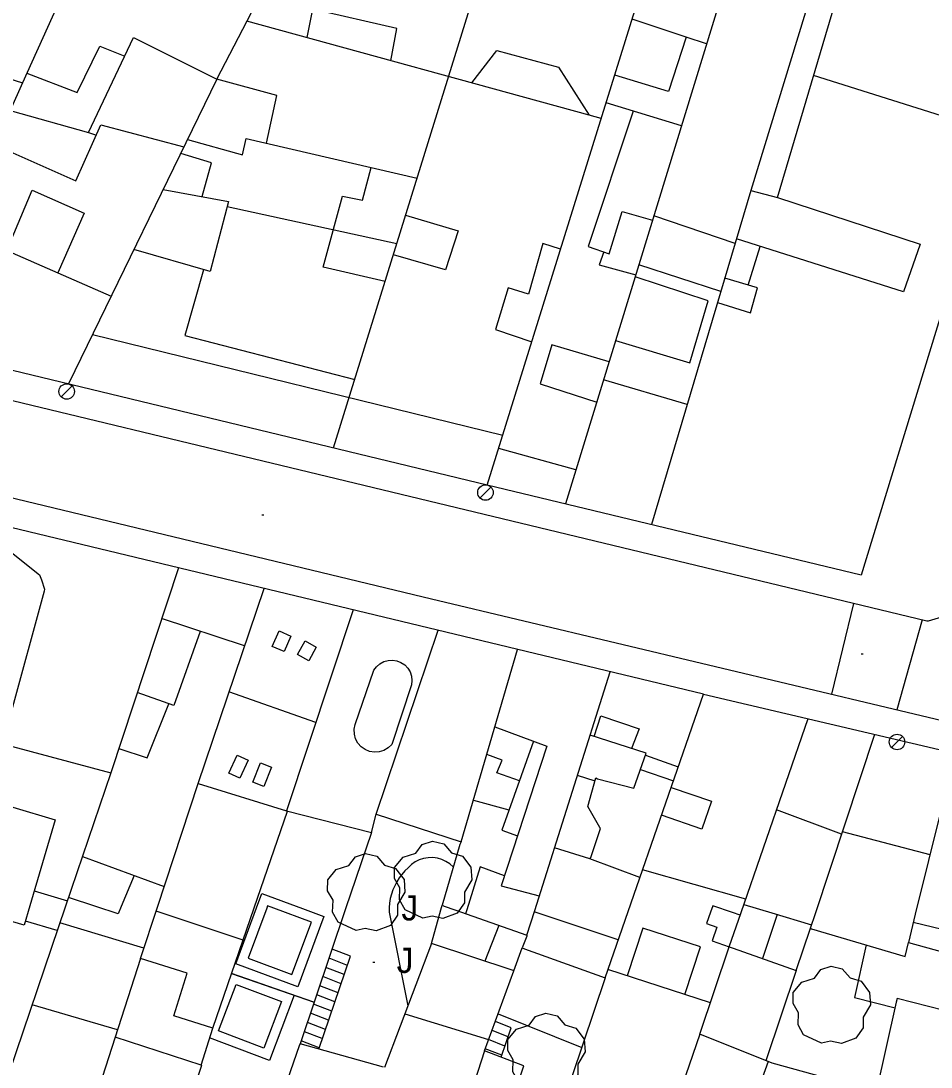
# Model space of a CAD drawing. Extents: x 431390 to 432653, y 4586754 to 4589600.
# Drawn here: x 432045.3 to 432092.3, y 4587636.5 to 4587690.5 of the extents above; entities that cross this region are included whole.
import ezdxf

# ---------------------------------------------------------------- set-up
doc = ezdxf.new("R2010")
doc.units = 0
for name, color, linetype in [('COM_17LS_LN', 7, 'Continuous'), ('COM_51_LN', 7, 'Continuous'), ('CON_01_LN', 7, 'Continuous'), ('CON_01FI_LN', 7, 'Continuous'), ('CON_03_LN', 7, 'Continuous'), ('CON_04_LN', 7, 'Continuous'), ('CON_07_LN', 7, 'Continuous'), ('CON_14LS_LN', 7, 'Continuous'), ('CON_15_LN', 7, 'Continuous'), ('CON_16_LN', 7, 'Continuous'), ('CON_23_LN', 7, 'Continuous'), ('CON_29_LN', 7, 'Continuous'), ('ENE_06_PT', 7, 'Continuous'), ('HID_11EX_LN', 7, 'Continuous'), ('HID_11IN_LN', 7, 'Continuous'), ('ORO_03_PT', 7, 'Continuous'), ('TOP_15JA_TX', 7, 'Continuous'), ('VEG_03_PT', 7, 'Continuous'), ('VEG_04_LN', 7, 'Continuous'), ('VEG_06_LN', 7, 'Continuous')]:
    doc.layers.add(name, color=color, linetype=linetype)

msp = doc.modelspace()

# ---------------------------------------------------------------- linework, layer by layer
at = {"layer": 'COM_17LS_LN'}
for points in [[(432006.024, 4587680.292), (432041.411, 4587756.509), (432044.673, 4587755.098), (432041.441, 4587748.129), (432031.405, 4587726.494), (432019.334, 4587700.469), (432009.569, 4587679.418), (432092.063, 4587659.53)], [(432092.063, 4587659.53), (432092.146, 4587659.541), (432092.826, 4587659.752), (432093.143, 4587659.912), (432093.715, 4587660.335), (432094.179, 4587660.874), (432094.362, 4587661.179), (432100.29, 4587680.016), (432111, 4587714.962), (432115.403, 4587729.599), (432115.334, 4587730.858), (432115.129, 4587731.674), (432114.803, 4587732.45), (432114.363, 4587733.167), (432113.819, 4587733.81), (432098.948, 4587740.984), (432087.838, 4587745.869), (432079.478, 4587749.815), (432077.122, 4587750.796)], [(431996.705, 4587653.49), (432007.414, 4587674.901), (432066.476, 4587660.674)], [(432066.476, 4587660.674), (432114.167, 4587649.302), (432121.083, 4587647.603), (432135.943, 4587643.954), (432158.866, 4587638.419)]]:
    msp.add_lwpolyline(points, dxfattribs=at)
at = {"layer": 'COM_51_LN'}
for points in [[(432087.153, 4587655.744), (432088.291, 4587660.441)], [(432091.821, 4587659.588), (432090.513, 4587654.942)]]:
    msp.add_lwpolyline(points, dxfattribs=at)
at = {"layer": 'CON_01_LN'}
for points in [[(432021.338, 4587700.513), (432047.183, 4587756.23), (432074.462, 4587750.012), (432092.863, 4587741.826), (432089.971, 4587731.966), (432092.685, 4587729.526), (432096.818, 4587726.785), (432106.854, 4587721.265), (432088.661, 4587661.894), (432069.351, 4587666.555)], [(432069.351, 4587666.555), (432012.008, 4587680.398), (432019.086, 4587695.657)], [(432080.515, 4587655.754), (432008.507, 4587673.078)], [(432080.515, 4587655.754), (432121.07, 4587646.224)]]:
    msp.add_lwpolyline(points, dxfattribs=at)
at = {"layer": 'CON_01FI_LN'}
for points in [[(432037.686, 4587692.072), (432036.767, 4587689.999), (432039.8, 4587688.515), (432040.023, 4587689.014), (432045.332, 4587687.328), (432044.693, 4587685.898), (432048.742, 4587684.772), (432051.08, 4587689.672), (432055.373, 4587687.519), (432063.231, 4587702.643)], [(432086.763, 4587694.198), (432082.971, 4587681.767), (432084.341, 4587681.402), (432088.05, 4587693.921), (432086.763, 4587694.198)], [(432047.563, 4587644.797), (432044.268, 4587635.081), (432006.82, 4587644.663), (432007.084, 4587645.187), (432015.694, 4587662.285), (432015.737, 4587662.272), (432034.19, 4587657.797), (432034.86, 4587660.208), (432035.137, 4587660.172), (432037.16, 4587659.697), (432037.143, 4587659.656), (432036.593, 4587657.168), (432036.755, 4587657.127), (432038.472, 4587656.7), (432038.755, 4587657.502), (432038.809, 4587657.469), (432040.297, 4587657.161), (432039.882, 4587656.377), (432039.414, 4587654.497), (432039.468, 4587654.474), (432049.901, 4587651.69), (432047.563, 4587644.797)], [(432053.422, 4587633.03), (432054.602, 4587636.574), (432054.567, 4587636.585), (432055.166, 4587638.492), (432053.15, 4587639.125), (432053.842, 4587641.329), (432051.434, 4587642.085), (432052.31, 4587644.752), (432054.407, 4587651.139)], [(432054.407, 4587651.139), (432058.983, 4587649.713), (432063.36, 4587648.605), (432063.605, 4587649.557), (432067.998, 4587648.114), (432067.93, 4587647.98), (432067.017, 4587644.843), (432067.116, 4587644.798), (432067.67, 4587644.604), (432071.398, 4587643.296), (432071.385, 4587643.243), (432071.151, 4587642.636), (432071.275, 4587642.597), (432075.437, 4587641.097), (432073.721, 4587635.974)], [(432080.339, 4587638.19), (432081.853, 4587642.698), (432082.054, 4587642.622), (432085.313, 4587641.466), (432086.042, 4587643.651), (432086.104, 4587643.625), (432090.935, 4587642.193), (432091.104, 4587642.919), (432096.913, 4587641.324), (432096.863, 4587641.194), (432096.183, 4587638.584), (432090.527, 4587640.017), (432090.482, 4587639.827), (432089.44, 4587635.201), (432084.065, 4587636.68), (432080.339, 4587638.19)], [(432070.208, 4587633.421), (432071.231, 4587636.549), (432071.178, 4587636.563), (432069.208, 4587637.32), (432070.728, 4587641.451), (432070.695, 4587641.471), (432066.472, 4587642.862), (432064.04, 4587636.456)], [(432063.986, 4587636.472), (432059.689, 4587637.682), (432059.654, 4587637.628), (432057.715, 4587632.046)]]:
    msp.add_lwpolyline(points, dxfattribs=at)
at = {"layer": 'CON_03_LN'}
for points in [[(432069.351, 4587666.555), (432083.88, 4587713.291)], [(432061.406, 4587668.473), (432075.16, 4587712.871)], [(432083.367, 4587698.099), (432073.392, 4587665.58)], [(432055.373, 4587687.519), (432047.718, 4587671.777)], [(432095.662, 4587684.74), (432086.209, 4587687.707)], [(432082.971, 4587681.767), (432077.833, 4587664.508)], [(432053.389, 4587662.28), (432049.901, 4587651.69)], [(432054.407, 4587651.139), (432057.817, 4587661.215)], [(432062.414, 4587660.109), (432058.983, 4587649.713)], [(432063.605, 4587649.557), (432066.808, 4587659.052)], [(432067.998, 4587648.114), (432070.907, 4587658.065)], [(432071.398, 4587643.296), (432071.799, 4587644.564), (432075.704, 4587656.911)], [(432075.437, 4587641.097), (432076.622, 4587644.518), (432080.515, 4587655.754)], [(432081.853, 4587642.698), (432082.461, 4587644.461), (432085.919, 4587654.484)], [(432086.042, 4587643.651), (432086.298, 4587644.424), (432089.365, 4587653.674)], [(432093.517, 4587652.699), (432091.463, 4587644.375), (432091.104, 4587642.919)], [(432051.613, 4587642.629), (432047.273, 4587643.942)], [(432051.434, 4587642.085), (432045.508, 4587623.69)], [(432080.878, 4587639.796), (432075.586, 4587641.528)], [(432080.339, 4587638.19), (432073.015, 4587616.91)], [(432069.208, 4587637.32), (432068.171, 4587634.125)], [(432083.856, 4587636.765), (432082.494, 4587632.997)]]:
    msp.add_lwpolyline(points, dxfattribs=at)
at = {"layer": 'CON_04_LN'}
for points in [[(432064.373, 4587688.477), (432064.669, 4587690.14), (432060.314, 4587691.142), (432060.028, 4587689.67)], [(432074.611, 4587685.667), (432056.932, 4587690.52)], [(432079.625, 4587689.692), (432076.832, 4587690.618)], [(432079.625, 4587689.692), (432078.71, 4587686.886), (432075.933, 4587687.727)], [(432080.681, 4587689.342), (432079.625, 4587689.692)], [(432068.559, 4587687.328), (432069.839, 4587689), (432073.026, 4587688.139), (432074.611, 4587685.667)], [(432057.947, 4587684.215), (432058.484, 4587686.685), (432055.373, 4587687.519)], [(432076.892, 4587685.877), (432074.57, 4587678.877), (432075.655, 4587678.492), (432076.321, 4587680.686), (432077.889, 4587680.239)], [(432079.386, 4587685.12), (432075.49, 4587686.302)], [(432075.239, 4587685.495), (432074.611, 4587685.667)], [(432043.898, 4587684.124), (432048.088, 4587682.264), (432049.392, 4587685.166), (432053.673, 4587684.023)], [(432048.742, 4587684.772), (432049.153, 4587684.635)], [(432053.857, 4587684.402), (432056.706, 4587683.611), (432056.895, 4587684.46), (432065.722, 4587682.406)], [(432054.623, 4587681.454), (432055.098, 4587683.197), (432053.51, 4587683.689)], [(432064.072, 4587677.078), (432060.878, 4587677.817), (432061.866, 4587681.479), (432062.901, 4587681.277), (432063.354, 4587682.957)], [(432044.533, 4587678.666), (432045.829, 4587681.781), (432048.52, 4587680.597), (432047.155, 4587677.517)], [(432052.6, 4587681.817), (432055.987, 4587681.21), (432055.036, 4587677.579), (432051.096, 4587678.724)], [(432084.341, 4587681.402), (432091.72, 4587678.994), (432090.858, 4587676.542), (432082.227, 4587679.269)], [(432065.128, 4587680.489), (432067.853, 4587679.688), (432067.188, 4587677.676), (432064.497, 4587678.452)], [(432082.155, 4587679.027), (432077.959, 4587680.467)], [(432073.14, 4587678.744), (432072.219, 4587679.033), (432071.478, 4587676.412), (432070.421, 4587676.739), (432069.772, 4587674.584), (432071.649, 4587673.948)], [(432082.822, 4587676.882), (432083.446, 4587678.884)], [(432044.533, 4587678.666), (432047.155, 4587677.517)], [(432075.364, 4587678.595), (432075.125, 4587677.934), (432077.021, 4587677.41)], [(432081.417, 4587676.547), (432077.18, 4587677.929)], [(432054.697, 4587677.677), (432053.729, 4587674.274), (432062.502, 4587672.011)], [(432075.981, 4587674.019), (432079.809, 4587672.864), (432080.757, 4587676.068), (432076.992, 4587677.317)], [(432081.25, 4587675.985), (432082.941, 4587675.454), (432083.312, 4587676.738), (432081.622, 4587677.236)], [(432048.959, 4587674.329), (432070.152, 4587669.131)], [(432075.641, 4587672.912), (432072.689, 4587673.798), (432072.076, 4587671.786), (432075.003, 4587670.831)], [(432073.929, 4587667.332), (432069.939, 4587668.447)], [(432044.454, 4587663.281), (432044.858, 4587662.991), (432046.225, 4587661.91), (432046.324, 4587661.657), (432046.467, 4587661.177), (432046.463, 4587661.068), (432044.713, 4587654.69), (432044.513, 4587654.761), (432041.515, 4587655.419), (432039.882, 4587656.377)], [(432056.81, 4587658.24), (432052.523, 4587659.651)], [(432054.523, 4587658.993), (432053.158, 4587655.159), (432051.264, 4587655.829)], [(432058.85, 4587657.945), (432058.238, 4587658.216), (432058.591, 4587659.015), (432059.203, 4587658.743), (432058.85, 4587657.945)], [(432060.123, 4587657.472), (432059.542, 4587657.793), (432059.936, 4587658.506), (432060.516, 4587658.185), (432060.123, 4587657.472)], [(432063.49, 4587656.984), (432063.626, 4587657.169), (432063.798, 4587657.32), (432064, 4587657.43), (432064.221, 4587657.494), (432064.45, 4587657.509), (432064.677, 4587657.473), (432064.891, 4587657.39), (432065.082, 4587657.262), (432065.24, 4587657.096), (432065.359, 4587656.899), (432065.432, 4587656.681), (432065.457, 4587656.453), (432065.432, 4587656.225), (432064.411, 4587653.144), (432064.228, 4587652.972), (432064.011, 4587652.846), (432063.771, 4587652.772), (432063.52, 4587652.755), (432063.272, 4587652.795), (432063.04, 4587652.89), (432062.836, 4587653.035), (432062.669, 4587653.223), (432062.55, 4587653.444), (432062.484, 4587653.686), (432062.474, 4587653.937), (432062.522, 4587654.184), (432063.49, 4587656.984)], [(432050.315, 4587652.947), (432051.775, 4587652.467), (432052.9, 4587655.25)], [(432074.878, 4587653.557), (432075.217, 4587654.632), (432077.204, 4587653.963), (432076.796, 4587652.944)], [(432069.735, 4587654.055), (432072.427, 4587653.062), (432070.067, 4587645.85), (432072.038, 4587645.321)], [(432077.233, 4587646.282), (432074.654, 4587647.238), (432074.707, 4587647.306), (432075.194, 4587648.814), (432075.168, 4587648.859), (432074.538, 4587649.937), (432074.966, 4587651.427), (432075.051, 4587651.37), (432076.929, 4587650.899), (432077.563, 4587652.699), (432074.665, 4587653.625)], [(432071.741, 4587653.315), (432070.096, 4587648.73), (432070.911, 4587648.43)], [(432056.423, 4587652.601), (432056.99, 4587652.346), (432056.567, 4587651.406), (432056, 4587651.66), (432056.423, 4587652.601)], [(432071.007, 4587651.27), (432069.85, 4587651.687), (432070.113, 4587652.338), (432069.319, 4587652.632)], [(432077.525, 4587652.59), (432079.215, 4587652.003)], [(432057.64, 4587652.205), (432058.208, 4587651.983), (432057.813, 4587650.974), (432057.245, 4587651.195), (432057.64, 4587652.205)], [(432077.267, 4587651.859), (432078.962, 4587651.271)], [(432074.916, 4587651.254), (432074.006, 4587651.541)], [(432078.845, 4587650.934), (432080.926, 4587650.214), (432080.43, 4587648.782), (432078.349, 4587649.502)], [(432068.631, 4587650.279), (432070.47, 4587649.772)], [(432074.654, 4587647.238), (432072.827, 4587647.815)], [(432048.432, 4587647.359), (432052.656, 4587645.805)], [(432070.232, 4587646.355), (432068.988, 4587646.823), (432068.289, 4587644.598), (432068.229, 4587644.408)], [(432082.703, 4587645.163), (432077.371, 4587646.681)], [(432051.104, 4587646.376), (432050.435, 4587644.77), (432050.283, 4587644.404), (432049.134, 4587644.782), (432047.716, 4587645.249)], [(432082.415, 4587644.327), (432082.014, 4587644.466), (432081, 4587644.816), (432080.883, 4587644.477), (432080.681, 4587643.893), (432081.213, 4587643.708), (432080.968, 4587643.005), (432081.853, 4587642.698)], [(432082.606, 4587644.88), (432084.058, 4587644.446), (432086.103, 4587643.835)], [(432076.114, 4587643.051), (432071.777, 4587644.495)], [(432084.321, 4587644.367), (432083.57, 4587642.084)], [(432105.114, 4587640.636), (432091.36, 4587643.957)], [(432079.563, 4587640.226), (432080.369, 4587642.687), (432077.388, 4587643.663), (432076.582, 4587641.202)], [(432050.251, 4587638.414), (432045.835, 4587639.701)], [(432054.567, 4587636.585), (432050.128, 4587638.031)]]:
    msp.add_lwpolyline(points, dxfattribs=at)
at = {"layer": 'CON_07_LN'}
for points in [[(432045.563, 4587687.839), (432048.165, 4587686.835), (432049.328, 4587689.234), (432050.622, 4587688.712)], [(432043.239, 4587644.448), (432043.353, 4587644.838), (432044.833, 4587649.904), (432047.021, 4587649.264), (432045.721, 4587644.815), (432045.427, 4587643.808), (432043.239, 4587644.448)], [(432045.947, 4587645.589), (432047.659, 4587645.079)], [(432047.135, 4587643.534), (432045.487, 4587644.015)], [(432069.947, 4587643.805), (432069.223, 4587641.956)], [(432070.728, 4587641.451), (432071.151, 4587642.636)], [(432088.917, 4587642.791), (432088.321, 4587640.076), (432090.418, 4587639.545)]]:
    msp.add_lwpolyline(points, dxfattribs=at)
at = {"layer": 'CON_14LS_LN'}
msp.add_lwpolyline([(432056.731, 4587643.041), (432052.238, 4587644.533)], dxfattribs=at)
at = {"layer": 'CON_15_LN'}
msp.add_lwpolyline([(432049.94, 4587697.527), (432045.332, 4587687.328)], dxfattribs=at)
at = {"layer": 'CON_16_LN'}
for points in [[(432055.166, 4587638.492), (432057.303, 4587644.703), (432059.023, 4587649.703)], [(432063.36, 4587648.605), (432062.033, 4587644.658), (432059.689, 4587637.682)], [(432066.472, 4587642.862), (432066.953, 4587644.611), (432067.017, 4587644.843)], [(432056.137, 4587641.314), (432060.41, 4587639.828)], [(432085.313, 4587641.466), (432083.745, 4587636.81)], [(432069.911, 4587639.232), (432074.228, 4587637.488)]]:
    msp.add_lwpolyline(points, dxfattribs=at)
at = {"layer": 'CON_23_LN'}
for points in [[(432060.64, 4587637.414), (432062.289, 4587642.211), (432061.335, 4587642.581)], [(432062.126, 4587641.737), (432061.175, 4587642.106)], [(432061.963, 4587641.264), (432061.016, 4587641.632)], [(432061.801, 4587640.791), (432060.857, 4587641.157)], [(432061.638, 4587640.318), (432060.697, 4587640.683)], [(432061.476, 4587639.845), (432060.538, 4587640.208)], [(432061.313, 4587639.372), (432060.378, 4587639.734)], [(432061.15, 4587638.899), (432060.219, 4587639.26)], [(432060.825, 4587637.952), (432059.9, 4587638.311)], [(432060.988, 4587638.426), (432060.06, 4587638.785)], [(432070.421, 4587638.039), (432069.594, 4587638.368)], [(432070.063, 4587636.991), (432070.583, 4587638.513), (432069.766, 4587638.838)], [(432060.662, 4587637.478), (432059.741, 4587637.836)], [(432070.259, 4587637.566), (432069.421, 4587637.899)], [(432070.097, 4587637.092), (432069.248, 4587637.43)]]:
    msp.add_lwpolyline(points, dxfattribs=at)
at = {"layer": 'CON_29_LN'}
for points in [[(432064.671, 4587679.012), (432055.914, 4587680.933)], [(432047.155, 4587677.517), (432049.92, 4587676.306)], [(432079.681, 4587670.716), (432075.356, 4587671.983)], [(432060.49, 4587654.278), (432056.006, 4587655.863)], [(432087.652, 4587648.507), (432084.293, 4587649.77)], [(432092.222, 4587647.452), (432087.696, 4587648.641)], [(432065.092, 4587639.227), (432069.421, 4587637.899)]]:
    msp.add_lwpolyline(points, dxfattribs=at)
at = {"layer": 'ENE_06_PT'}
for p, q in [((432047.906, 4587671.671), (432047.34, 4587671.105)), ((432069.539, 4587666.449), (432068.973, 4587665.883)), ((432090.801, 4587653.562), (432090.235, 4587652.996))]:
    msp.add_line(p, q, dxfattribs=at)
for centre in [(432047.623, 4587671.388), (432069.256, 4587666.166), (432090.518, 4587653.279)]:
    msp.add_circle(centre, 0.4, dxfattribs=at)
at = {"layer": 'HID_11EX_LN'}
for points in [[(432059.797, 4587644.679), (432060.903, 4587644.27), (432059.554, 4587640.629), (432056.353, 4587641.811), (432057.423, 4587644.702), (432057.702, 4587645.455), (432059.797, 4587644.679)], [(432059.37, 4587640.19), (432058.096, 4587636.819), (432055.007, 4587637.987)]]:
    msp.add_lwpolyline(points, dxfattribs=at)
at = {"layer": 'HID_11IN_LN'}
for points in [[(432058.322, 4587644.694), (432057.997, 4587644.814), (432057.954, 4587644.697), (432056.995, 4587642.107), (432059.26, 4587641.27), (432060.262, 4587643.976), (432058.322, 4587644.694)], [(432057.806, 4587637.463), (432055.464, 4587638.349), (432056.372, 4587640.751), (432058.714, 4587639.864), (432057.806, 4587637.463)]]:
    msp.add_lwpolyline(points, dxfattribs=at)
at = {"layer": 'ORO_03_PT'}
for p, q in [((432057.71, 4587665.019), (432057.81, 4587665.019)), ((432088.672, 4587657.83), (432088.772, 4587657.83)), ((432063.433, 4587641.896), (432063.533, 4587641.896))]:
    msp.add_line(p, q, dxfattribs=at)
at = {"layer": 'VEG_03_PT'}
for points in [[(432066.028, 4587644.169), (432065.101, 4587644.604), (432064.813, 4587645.125), (432064.836, 4587645.739), (432064.554, 4587646.231), (432064.562, 4587646.794), (432065.003, 4587647.329), (432065.656, 4587647.533), (432065.991, 4587647.984), (432066.517, 4587648.154), (432067.097, 4587648.021), (432067.497, 4587647.555), (432068.071, 4587647.385), (432068.505, 4587646.802), (432068.554, 4587646.16), (432068.171, 4587645.513), (432068.171, 4587644.963), (432067.799, 4587644.429), (432067.06, 4587644.154), (432066.495, 4587644.282), (432066.028, 4587644.169)], [(432062.572, 4587643.532), (432061.645, 4587643.967), (432061.357, 4587644.488), (432061.38, 4587645.102), (432061.098, 4587645.594), (432061.106, 4587646.157), (432061.547, 4587646.692), (432062.2, 4587646.896), (432062.535, 4587647.347), (432063.061, 4587647.517), (432063.641, 4587647.384), (432064.041, 4587646.918), (432064.615, 4587646.748), (432065.049, 4587646.165), (432065.098, 4587645.523), (432064.715, 4587644.876), (432064.715, 4587644.326), (432064.343, 4587643.792), (432063.604, 4587643.517), (432063.039, 4587643.645), (432062.572, 4587643.532)], [(432086.621, 4587637.709), (432085.694, 4587638.144), (432085.406, 4587638.665), (432085.429, 4587639.279), (432085.147, 4587639.771), (432085.155, 4587640.334), (432085.596, 4587640.869), (432086.249, 4587641.073), (432086.584, 4587641.524), (432087.11, 4587641.694), (432087.69, 4587641.561), (432088.09, 4587641.095), (432088.664, 4587640.925), (432089.098, 4587640.342), (432089.147, 4587639.7), (432088.764, 4587639.053), (432088.764, 4587638.503), (432088.392, 4587637.969), (432087.653, 4587637.694), (432087.088, 4587637.822), (432086.621, 4587637.709)], [(432071.883, 4587635.283), (432070.956, 4587635.718), (432070.668, 4587636.239), (432070.691, 4587636.853), (432070.409, 4587637.345), (432070.417, 4587637.908), (432070.858, 4587638.443), (432071.511, 4587638.647), (432071.846, 4587639.098), (432072.372, 4587639.268), (432072.952, 4587639.135), (432073.352, 4587638.669), (432073.926, 4587638.499), (432074.36, 4587637.916), (432074.409, 4587637.274), (432074.026, 4587636.627), (432074.026, 4587636.077), (432073.654, 4587635.543), (432072.915, 4587635.268), (432072.35, 4587635.396), (432071.883, 4587635.283)]]:
    msp.add_lwpolyline(points, dxfattribs=at)
at = {"layer": 'VEG_04_LN'}
msp.add_lwpolyline([(432060.344, 4587639.85), (432056.138, 4587641.318)], dxfattribs=at)
at = {"layer": 'VEG_06_LN'}
msp.add_lwpolyline([(432067.594, 4587646.826), (432067.415, 4587646.983), (432067.216, 4587647.111), (432066.999, 4587647.209), (432066.771, 4587647.274), (432066.535, 4587647.305), (432066.298, 4587647.3), (432066.063, 4587647.26), (432065.838, 4587647.186), (432065.625, 4587647.079), (432065.431, 4587646.943), (432065.26, 4587646.779), (432065.092, 4587646.615), (432064.939, 4587646.439), (432064.799, 4587646.252), (432064.674, 4587646.055), (432064.566, 4587645.848), (432064.473, 4587645.633), (432064.398, 4587645.412), (432064.341, 4587645.186), (432064.301, 4587644.956), (432064.279, 4587644.723), (432064.278, 4587644.636), (432064.276, 4587644.49), (432065.248, 4587639.638)], dxfattribs=at)

# ---------------------------------------------------------------- texts
at = {"layer": 'TOP_15JA_TX'}
for p in [(432064.916, 4587644.056), (432064.667, 4587641.345)]:
    msp.add_text('J', height=1.3, dxfattribs=at).set_placement(p)

doc.saveas('drawing.dxf')
